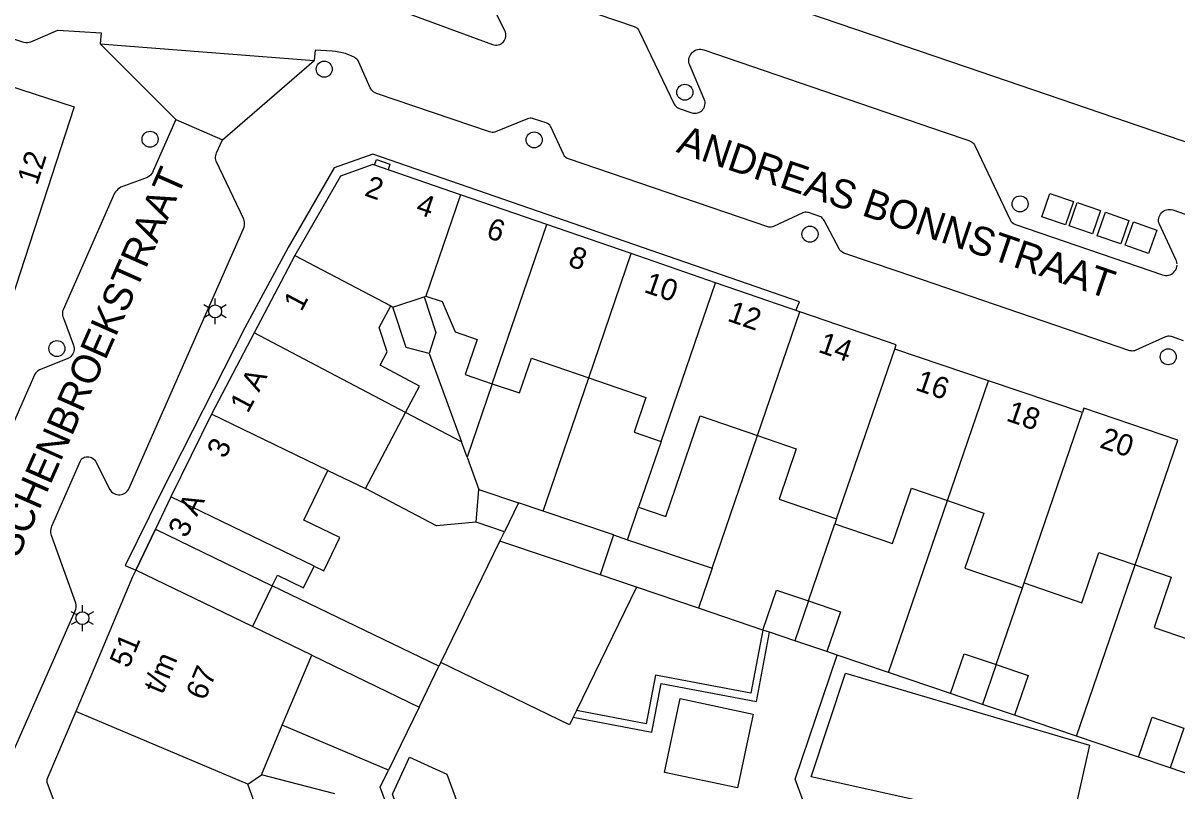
# Model space of a CAD drawing. Extents: x 122462 to 123306, y 485548 to 486417.
# Drawn here: x 122543.2 to 122623.8, y 485839.9 to 485893.5 of the extents above; entities that cross this region are included whole.
import ezdxf

# ---------------------------------------------------------------- set-up
doc = ezdxf.new("R2010")
doc.units = 0
for name, color, linetype in [('B-WE-IE-MEUBILAIR_WEGMEUBILAIR_VERKEERSBORD-S', 7, 'Continuous'), ('Level 1', 7, 'Continuous'), ('Level 10', 7, 'Continuous'), ('Level 11', 7, 'Continuous'), ('Level 17', 7, 'Continuous'), ('Level 19', 7, 'Continuous'), ('Level 2', 7, 'Continuous'), ('Level 21', 7, 'Continuous'), ('Level 4', 7, 'Continuous'), ('Level 40', 7, 'Continuous'), ('Level 42', 7, 'Continuous'), ('Level 50', 7, 'Continuous'), ('Level 53', 7, 'Continuous'), ('N werkgrens', 7, 'Continuous'), ('N-WE-AL-T25', 7, 'Continuous'), ('N-WE-GR-BOOM_DOORWORTELBARE RUIMTE-G', 7, 'Continuous')]:
    doc.layers.add(name, color=color, linetype=linetype)

msp = doc.modelspace()

# ---------------------------------------------------------------- linework, layer by layer
at = {"layer": 'Level 1'}
for p, q in [((122579.784, 485879.419), (122573.755, 485881.5)), ((122585.673, 485877.387), (122579.784, 485879.419)), ((122562.199, 485877.259), (122559.357, 485871.865)), ((122591.562, 485875.354), (122585.673, 485877.387)), ((122597.449, 485873.319), (122591.562, 485875.354)), ((122569.031, 485873.661), (122571.216, 485874.378)), ((122571.216, 485874.378), (122571.328, 485874.415)), ((122568.882, 485873.74), (122569.031, 485873.661)), ((122559.357, 485871.865), (122556.36, 485866.179)), ((122610.631, 485868.505), (122604.076, 485870.72)), ((122617.186, 485866.29), (122610.631, 485868.505)), ((122567.125, 485860.979), (122569.927, 485866.294)), ((122556.36, 485866.179), (122553.539, 485860.4)), ((122587.764, 485864.269), (122586.194, 485859.684)), ((122564.499, 485862.248), (122567.125, 485860.979)), ((122553.539, 485860.4), (122552.459, 485858.14)), ((122600.02, 485858.876), (122599.901, 485858.529)), ((122552.459, 485858.14), (122560.61, 485854.202)), ((122563.373, 485849.35), (122551.08, 485855.289)), ((122612.992, 485854.044), (122613.111, 485854.392)), ((122561.31, 485844.461), (122563.373, 485849.35)), ((122559.851, 485841.002), (122561.31, 485844.461)), ((122558.901, 485840.349), (122559.851, 485841.002)), ((122559.59, 485838.478), (122558.901, 485840.349))]:
    msp.add_line(p, q, dxfattribs=at)
for points in [[(122579.039, 485900.679), (122609.071, 485890.432), (122627.809, 485884.039), (122627.989, 485884.549), (122627.707, 485884.649), (122627.853, 485885.077)], [(122531.929, 485892.459), (122546.779, 485887.63), (122540.489, 485868.38)], [(122573.755, 485881.5), (122567.64, 485883.61), (122565.37, 485882.799), (122562.199, 485877.259)], [(122571.328, 485874.415), (122572.473, 485874.048), (122573.373, 485871.919), (122574.92, 485871.389), (122574.086, 485868.954), (122575.978, 485868.306)], [(122569.927, 485866.294), (122570.9, 485868.14), (122568.142, 485869.594), (122568.637, 485870.533), (122568.081, 485872.22), (122568.882, 485873.74)], [(122604.076, 485870.72), (122604.179, 485871.029), (122602.696, 485871.534), (122597.449, 485873.319)], [(122575.978, 485868.306), (122577.871, 485867.658), (122578.705, 485870.092), (122582.706, 485868.722)], [(122582.706, 485868.722), (122586.707, 485867.351), (122585.873, 485864.917), (122587.764, 485864.269)], [(122623.84, 485864.36), (122617.289, 485866.6), (122617.186, 485866.29)], [(122586.194, 485859.684), (122588.087, 485859.036), (122590.492, 485866.055), (122594.493, 485864.685)], [(122594.493, 485864.685), (122597.2, 485863.758), (122596, 485860.253), (122600.02, 485858.876)], [(122563.528, 485855.575), (122564.206, 485855.248), (122565.327, 485857.569), (122562.823, 485858.78), (122564.499, 485862.248)], [(122599.901, 485858.529), (122603.921, 485857.152), (122605.24, 485861.004), (122607.765, 485860.139)], [(122607.765, 485860.139), (122610.292, 485859.274), (122608.972, 485855.42), (122612.992, 485854.044)], [(122613.111, 485854.392), (122617.132, 485853.015), (122618.333, 485856.521), (122620.859, 485855.655)], [(122551.08, 485855.289), (122550.86, 485854.829), (122548.166, 485848.445), (122546.889, 485845.419)], [(122560.61, 485854.202), (122560.969, 485854.946), (122562.797, 485854.062), (122563.528, 485855.575)], [(122620.859, 485855.655), (122623.385, 485854.79), (122622.185, 485851.285), (122626.205, 485849.908)], [(122546.889, 485845.419), (122544.88, 485840.66), (122544.88, 485840.489), (122548.508, 485830.759)]]:
    msp.add_lwpolyline(points, dxfattribs=at)
at = {"layer": 'Level 10'}
msp.add_lwpolyline([(122551.08, 485855.289), (122552.459, 485858.14), (122560.61, 485854.202), (122559.232, 485851.352), (122551.08, 485855.289)], dxfattribs=at)
at = {"layer": 'Level 11'}
msp.add_lwpolyline([(122597.176, 485873.416), (122597.427, 485874.032), (122567.638, 485884.325), (122564.924, 485883.389), (122561.714, 485877.82), (122558.692, 485872.216), (122552.845, 485860.698), (122550.35, 485855.621), (122551.08, 485855.289)], dxfattribs=at)
at = {"layer": 'Level 17'}
for p, q in [((122548.595, 485892.043), (122553.885, 485886.747)), ((122548.595, 485892.043), (122563.545, 485890.867)), ((122557.131, 485885.342), (122563.545, 485890.867)), ((122553.885, 485886.747), (122557.131, 485885.342)), ((122552.459, 485858.14), (122551.08, 485855.289))]:
    msp.add_line(p, q, dxfattribs=at)
for points in [[(122576.695, 485896.389), (122585.892, 485893.241), (122585.979, 485893.203), (122586.06, 485893.151), (122586.131, 485893.088), (122586.191, 485893.014), (122586.239, 485892.932), (122588.681, 485887.836), (122588.729, 485887.754), (122588.789, 485887.68), (122588.86, 485887.617), (122588.941, 485887.566), (122589.028, 485887.528), (122589.909, 485887.227), (122590.006, 485887.201), (122590.106, 485887.19), (122590.207, 485887.193), (122590.306, 485887.21), (122590.402, 485887.242), (122590.492, 485887.286), (122590.575, 485887.344), (122590.649, 485887.413), (122590.712, 485887.491), (122590.763, 485887.578), (122590.801, 485887.671), (122590.825, 485887.769), (122590.835, 485887.869), (122590.831, 485887.97), (122590.812, 485888.069), (122590.779, 485888.164), (122589.761, 485890.549), (122589.725, 485890.651), (122589.704, 485890.757), (122589.697, 485890.865), (122589.705, 485890.973), (122589.727, 485891.079), (122589.763, 485891.181), (122589.813, 485891.277), (122589.875, 485891.366), (122589.948, 485891.445), (122590.032, 485891.514), (122590.124, 485891.571), (122590.223, 485891.615), (122590.327, 485891.645), (122590.434, 485891.661)], [(122569.21, 485894.489), (122575.986, 485891.987), (122576.086, 485891.958), (122576.189, 485891.945), (122576.293, 485891.946), (122576.396, 485891.964), (122576.495, 485891.996), (122576.588, 485892.042), (122576.673, 485892.102), (122576.748, 485892.174), (122576.812, 485892.256), (122576.863, 485892.347), (122576.9, 485892.444), (122576.922, 485892.546), (122576.929, 485892.649), (122576.921, 485892.753), (122576.897, 485892.854), (122576.858, 485892.951), (122575.699, 485895.32)], [(122534.539, 485895.051), (122543.162, 485892.177), (122543.277, 485892.147), (122543.395, 485892.133), (122543.513, 485892.134), (122543.631, 485892.151), (122543.745, 485892.182), (122545.646, 485892.994), (122548.673, 485892.799), (122548.595, 485892.043)], [(122600.372, 485877.511), (122600.303, 485877.57), (122600.243, 485877.638), (122600.195, 485877.715), (122599.141, 485879.71), (122599.097, 485879.78), (122599.044, 485879.844), (122598.982, 485879.9), (122598.913, 485879.947), (122598.839, 485879.984), (122598.067, 485880.249), (122597.987, 485880.27), (122597.904, 485880.28), (122597.821, 485880.279), (122597.739, 485880.266), (122597.659, 485880.242), (122595.618, 485879.285), (122595.54, 485879.255), (122595.459, 485879.236), (122595.377, 485879.229), (122595.294, 485879.233), (122595.212, 485879.248), (122581.293, 485884.002), (122581.203, 485884.041), (122581.121, 485884.094), (122581.049, 485884.16), (122580.988, 485884.237), (122580.94, 485884.322), (122580.091, 485886.192), (122580.044, 485886.277), (122579.983, 485886.354), (122579.911, 485886.42), (122579.829, 485886.473), (122579.739, 485886.512), (122578.865, 485886.811), (122578.782, 485886.833), (122578.697, 485886.843), (122578.611, 485886.84), (122578.527, 485886.825), (122578.445, 485886.799), (122576.211, 485885.893), (122576.13, 485885.867), (122576.045, 485885.852), (122575.96, 485885.85), (122575.875, 485885.86), (122575.792, 485885.882), (122567.898, 485888.57), (122567.803, 485888.61), (122567.714, 485888.662), (122567.633, 485888.726), (122567.562, 485888.801), (122567.502, 485888.885), (122567.454, 485888.976), (122566.667, 485890.747), (122566.627, 485890.826), (122566.578, 485890.899), (122566.52, 485890.966), (122566.455, 485891.025), (122566.383, 485891.076), (122566.169, 485891.181), (122565.949, 485891.273), (122565.724, 485891.352), (122565.494, 485891.416), (122565.261, 485891.467), (122565.025, 485891.503), (122564.788, 485891.525), (122563.62, 485891.6), (122563.545, 485890.867)], [(122590.434, 485891.661), (122590.542, 485891.662), (122590.649, 485891.649), (122590.754, 485891.621), (122607.533, 485885.874), (122609.251, 485885.286), (122609.346, 485885.25), (122609.435, 485885.2), (122609.516, 485885.139), (122609.588, 485885.067), (122609.649, 485884.986), (122609.698, 485884.897), (122612.139, 485879.744), (122612.194, 485879.66), (122612.261, 485879.585), (122612.338, 485879.52), (122612.422, 485879.466), (122612.514, 485879.424), (122622.778, 485875.903), (122622.882, 485875.876), (122622.989, 485875.865), (122623.096, 485875.868), (122623.202, 485875.885), (122623.304, 485875.918), (122623.401, 485875.964), (122623.49, 485876.023), (122623.571, 485876.095), (122623.64, 485876.176), (122623.698, 485876.267), (122623.743, 485876.364), (122623.773, 485876.467), (122623.789, 485876.573)], [(122553.885, 485886.747), (122552.306, 485883.166), (122552.255, 485883.06), (122552.19, 485882.961), (122552.112, 485882.872), (122552.024, 485882.794), (122551.926, 485882.729), (122551.82, 485882.677), (122550.046, 485882.033), (122549.939, 485881.968), (122549.84, 485881.892), (122549.749, 485881.806), (122549.668, 485881.71), (122549.597, 485881.607), (122546.006, 485873.474), (122545.976, 485873.376), (122545.959, 485873.275), (122545.957, 485873.173), (122545.968, 485873.072), (122545.993, 485872.973), (122546.032, 485872.878), (122546.732, 485871.003), (122546.762, 485870.9), (122546.778, 485870.794), (122546.777, 485870.686), (122546.761, 485870.58), (122546.73, 485870.478), (122546.685, 485870.38), (122546.625, 485870.291), (122546.554, 485870.211), (122546.471, 485870.142), (122546.38, 485870.086), (122546.281, 485870.044), (122544.365, 485869.28), (122544.286, 485869.236), (122544.213, 485869.183), (122544.148, 485869.12), (122544.091, 485869.05), (122544.044, 485868.973), (122540.594, 485861.168)], [(122546.893, 485852.552), (122546.915, 485852.657), (122546.922, 485852.764), (122546.912, 485852.871), (122546.887, 485852.976), (122545.207, 485857.701), (122545.176, 485857.809), (122545.159, 485857.921), (122545.156, 485858.033), (122545.167, 485858.145), (122545.192, 485858.255), (122545.23, 485858.361), (122547.218, 485862.926), (122547.276, 485863.004), (122547.346, 485863.071), (122547.426, 485863.127), (122547.513, 485863.169), (122547.607, 485863.196), (122547.703, 485863.208), (122547.8, 485863.205), (122547.895, 485863.187), (122547.987, 485863.153), (122548.071, 485863.106), (122548.147, 485863.045), (122548.213, 485862.973), (122548.266, 485862.892), (122548.305, 485862.803), (122549.264, 485860.925), (122549.322, 485860.837), (122549.392, 485860.757), (122549.473, 485860.689), (122549.562, 485860.632), (122549.658, 485860.588), (122549.76, 485860.559), (122549.865, 485860.544), (122549.97, 485860.544), (122550.075, 485860.558), (122550.177, 485860.587), (122550.273, 485860.631), (122550.363, 485860.687), (122550.444, 485860.755), (122550.514, 485860.834), (122550.572, 485860.923), (122550.618, 485861.018), (122558.654, 485879.226), (122558.676, 485879.341), (122558.684, 485879.458), (122558.679, 485879.575), (122558.659, 485879.691), (122558.626, 485879.803), (122556.702, 485883.84), (122556.674, 485883.934), (122556.658, 485884.031), (122556.654, 485884.13), (122556.663, 485884.227), (122556.685, 485884.323), (122556.718, 485884.416), (122557.131, 485885.342)], [(122623.791, 485876.681), (122623.777, 485876.787), (122623.748, 485876.89), (122623.706, 485876.989), (122622.554, 485879.44), (122622.521, 485879.541), (122622.503, 485879.646), (122622.5, 485879.753), (122622.512, 485879.859), (122622.538, 485879.962), (122622.579, 485880.061), (122622.634, 485880.152), (122622.701, 485880.235), (122622.779, 485880.308), (122622.867, 485880.369), (122622.962, 485880.416), (122623.063, 485880.45), (122623.168, 485880.469), (122623.274, 485880.474), (122623.381, 485880.463), (122623.484, 485880.437), (122627.732, 485878.954)], [(122624.231, 485871.308), (122623.401, 485871.592), (122623.321, 485871.613), (122623.238, 485871.623), (122623.155, 485871.622), (122623.073, 485871.609), (122622.994, 485871.585), (122620.905, 485870.639), (122620.827, 485870.61), (122620.746, 485870.592), (122620.663, 485870.585), (122620.58, 485870.59), (122620.499, 485870.606), (122604.255, 485876.156), (122600.532, 485877.428), (122600.449, 485877.464), (122600.372, 485877.511)], [(122542.531, 485842.602), (122545.6, 485849.59), (122546.856, 485852.451), (122546.893, 485852.552)]]:
    msp.add_lwpolyline(points, dxfattribs=at)
at = {"layer": 'Level 19'}
for p, q in [((122571.559, 485870.416), (122573.827, 485864.238)), ((122579.517, 485859.408), (122582.706, 485868.722)), ((122575.978, 485868.306), (122574.219, 485863.17)), ((122573.827, 485864.238), (122569.927, 485866.294)), ((122591.318, 485855.414), (122594.493, 485864.685)), ((122574.219, 485863.17), (122573.827, 485864.238)), ((122574.219, 485863.17), (122575.044, 485860.923)), ((122603.652, 485848.129), (122607.765, 485860.139)), ((122585.416, 485857.411), (122586.194, 485859.684)), ((122598.053, 485853.133), (122599.901, 485858.529)), ((122616.761, 485843.691), (122620.859, 485855.655)), ((122572.254, 485848.574), (122560.61, 485854.202)), ((122611.161, 485848.694), (122612.992, 485854.044)), ((122594.874, 485851.102), (122590.364, 485852.629)), ((122563.373, 485849.35), (122570.861, 485845.709)), ((122600.057, 485849.346), (122599.326, 485849.594)), ((122603.652, 485848.129), (122600.057, 485849.346)), ((122572.385, 485848.843), (122572.254, 485848.574)), ((122607.981, 485846.664), (122603.652, 485848.129)), ((122570.861, 485845.709), (122568.731, 485841.33)), ((122616.761, 485843.691), (122612.433, 485845.157)), ((122568.731, 485841.33), (122561.31, 485844.461)), ((122621.09, 485842.225), (122616.761, 485843.691)), ((122564.979, 485839.658), (122559.851, 485841.002))]:
    msp.add_line(p, q, dxfattribs=at)
for points in [[(122571.216, 485874.378), (122572.035, 485871.882), (122571.559, 485870.416)], [(122571.559, 485870.416), (122569.959, 485870.832), (122569.031, 485873.661)], [(122574.85, 485858.629), (122572.071, 485858.372), (122567.125, 485860.979)], [(122593.099, 485840.081), (122587.999, 485841.161), (122589.091, 485846.321), (122594.191, 485845.241), (122593.099, 485840.081)], [(122568.675, 485838.69), (122568.146, 485840.126), (122568.731, 485841.33)]]:
    msp.add_lwpolyline(points, dxfattribs=at)
at = {"layer": 'Level 2'}
for p, q in [((122574.85, 485858.629), (122575.044, 485860.923)), ((122575.044, 485860.923), (122577.804, 485859.988)), ((122577.804, 485859.988), (122576.819, 485857.962)), ((122579.517, 485859.408), (122577.804, 485859.988)), ((122584.442, 485857.741), (122579.517, 485859.408)), ((122576.819, 485857.962), (122574.85, 485858.629)), ((122576.507, 485857.32), (122576.819, 485857.962)), ((122584.442, 485857.741), (122583.498, 485854.953)), ((122584.442, 485857.741), (122585.416, 485857.411)), ((122585.416, 485857.411), (122591.318, 485855.414)), ((122572.385, 485848.843), (122576.507, 485857.32)), ((122583.498, 485854.953), (122576.507, 485857.32)), ((122591.318, 485855.414), (122590.364, 485852.629)), ((122586.039, 485854.093), (122583.498, 485854.953)), ((122586.039, 485854.093), (122581.852, 485845.481)), ((122590.364, 485852.629), (122586.039, 485854.093)), ((122598.053, 485853.133), (122597.099, 485850.348)), ((122595.341, 485850.944), (122594.874, 485851.102)), ((122597.099, 485850.348), (122595.341, 485850.944)), ((122599.326, 485849.594), (122597.099, 485850.348)), ((122611.161, 485848.694), (122610.207, 485845.91)), ((122610.207, 485845.91), (122607.981, 485846.664)), ((122581.852, 485845.481), (122581.625, 485845.014)), ((122612.433, 485845.157), (122610.207, 485845.91)), ((122624.27, 485844.256), (122623.316, 485841.471)), ((122623.316, 485841.471), (122621.09, 485842.225)), ((122625.542, 485840.717), (122623.316, 485841.471))]:
    msp.add_line(p, q, dxfattribs=at)
for points in [[(122594.874, 485851.102), (122595.827, 485853.887), (122598.053, 485853.133)], [(122598.053, 485853.133), (122600.28, 485852.38), (122599.326, 485849.594)], [(122607.981, 485846.664), (122608.934, 485849.448), (122611.161, 485848.694)], [(122581.625, 485845.014), (122581.364, 485844.477), (122572.385, 485848.843)], [(122611.161, 485848.694), (122613.386, 485847.941), (122612.433, 485845.157)], [(122616.29, 485836.845), (122598.241, 485840.86), (122600.637, 485848.095), (122617.676, 485843.074), (122616.29, 485836.845)], [(122621.09, 485842.225), (122622.044, 485845.01), (122624.27, 485844.256)], [(122574.438, 485824.874), (122569, 485839.633), (122570.199, 485842.231), (122572.797, 485841.032), (122578.235, 485826.273), (122574.438, 485824.874)]]:
    msp.add_lwpolyline(points, dxfattribs=at)
at = {"layer": 'Level 21'}
for points in [[(122594.874, 485851.102), (122594.023, 485846.688), (122587.362, 485847.956), (122586.715, 485844.556), (122581.852, 485845.481)], [(122581.625, 485845.014), (122587.112, 485843.971), (122587.759, 485847.37), (122594.42, 485846.103), (122595.341, 485850.944)]]:
    msp.add_lwpolyline(points, dxfattribs=at)
at = {"layer": 'Level 4'}
for p, q in [((122575.978, 485868.306), (122579.784, 485879.419)), ((122582.706, 485868.722), (122585.673, 485877.387)), ((122587.764, 485864.269), (122591.562, 485875.354)), ((122594.493, 485864.685), (122597.449, 485873.319)), ((122569.927, 485866.294), (122559.357, 485871.865)), ((122600.02, 485858.876), (122604.076, 485870.72)), ((122607.765, 485860.139), (122610.631, 485868.505)), ((122613.111, 485854.392), (122617.186, 485866.29)), ((122564.499, 485862.248), (122556.36, 485866.179)), ((122620.859, 485855.655), (122623.84, 485864.36)), ((122558.901, 485840.349), (122546.889, 485845.419))]:
    msp.add_line(p, q, dxfattribs=at)
at = {"layer": 'Level 40'}
msp.add_lwpolyline([(122567.75, 485883.573), (122567.883, 485883.957), (122568.828, 485883.629), (122568.696, 485883.247)], dxfattribs=at)
at = {"layer": 'Level 42'}
for points in [[(122615.991, 485879.404), (122614.358, 485879.962), (122614.916, 485881.595), (122616.549, 485881.037), (122615.991, 485879.404)], [(122617.897, 485878.765), (122616.265, 485879.323), (122616.823, 485880.955), (122618.455, 485880.397), (122617.897, 485878.765)], [(122619.854, 485878.067), (122618.215, 485878.64), (122618.788, 485880.279), (122620.427, 485879.706), (122619.854, 485878.067)], [(122621.796, 485877.395), (122620.166, 485877.981), (122620.752, 485879.611), (122622.382, 485879.025), (122621.796, 485877.395)]]:
    msp.add_lwpolyline(points, dxfattribs=at)
at = {"layer": 'Level 50'}
for p, q in [((122556.233, 485873.579), (122555.843, 485873.804)), ((122556.623, 485873.804), (122556.623, 485874.254)), ((122557.402, 485873.804), (122557.012, 485873.579)), ((122556.233, 485873.129), (122555.843, 485872.904)), ((122556.623, 485872.454), (122556.623, 485872.904)), ((122557.402, 485872.904), (122557.012, 485873.129)), ((122547.358, 485852.384), (122547.358, 485852.834)), ((122546.968, 485852.159), (122546.578, 485852.384)), ((122548.137, 485852.384), (122547.747, 485852.159)), ((122546.968, 485851.709), (122546.578, 485851.484)), ((122547.358, 485851.034), (122547.358, 485851.484)), ((122548.137, 485851.484), (122547.747, 485851.709))]:
    msp.add_line(p, q, dxfattribs=at)
for centre in [(122556.623, 485873.354), (122547.358, 485851.934)]:
    msp.add_circle(centre, 0.45, dxfattribs=at)
at = {"layer": 'Level 53'}
for centre in [(122564.244, 485890.268), (122589.42, 485888.659), (122552.078, 485885.375), (122578.901, 485885.332), (122612.83, 485880.858), (122598.16, 485878.748), (122545.576, 485870.76), (122623.174, 485870.184)]:
    msp.add_circle(centre, 0.56, dxfattribs=at)
at = {"layer": 'N werkgrens'}
msp.add_line((122570.861, 485845.709), (122572.254, 485848.574), dxfattribs=at)
msp.add_lwpolyline([(122600.735, 485830.91), (122597.129, 485840.696), (122600.057, 485849.346)], dxfattribs=at)
at = {"layer": 'N-WE-AL-T25'}
for p, q in [((122573.755, 485881.5), (122571.328, 485874.415)), ((122573.755, 485881.501), (122573.755, 485881.5)), ((122562.199, 485877.259), (122568.882, 485873.74)), ((122563.528, 485855.575), (122553.539, 485860.4))]:
    msp.add_line(p, q, dxfattribs=at)

# ---------------------------------------------------------------- texts
at = {"layer": 'B-WE-IE-MEUBILAIR_WEGMEUBILAIR_VERKEERSBORD-S'}
for s, rotation, p in [('12', 71.905, (122544.189, 485882.11)), ('2', 340.95744, (122566.983, 485881.459)), ('4', 340.95744, (122570.563, 485880.222)), ('6', 340.95744, (122575.477, 485878.526)), ('8', 340.95744, (122581.198, 485876.551)), ('10', 340.95431, (122586.491, 485874.724)), ('1', 62.21284, (122562.648, 485873.283)), ('12', 340.9744, (122592.315, 485872.714)), ('14', 340.9744, (122598.664, 485870.536)), ('1 A', 62.19617, (122558.906, 485866.184)), ('16', 340.9744, (122605.442, 485867.891)), ('18', 340.9744, (122611.786, 485865.747)), ('20', 340.9744, (122618.314, 485863.878)), ('3', 63.98283, (122557.32, 485863.014)), ('3 A', 64.07066, (122554.619, 485857.472)), ('51', 67.1149, (122550.575, 485848.366)), ('t/m', 67.1149, (122552.946, 485846.551)), ('67', 67.1149, (122555.9, 485846.119))]:
    msp.add_text(s, height=1.5, rotation=rotation, dxfattribs=at).set_placement(p)
at = {"layer": 'N-WE-GR-BOOM_DOORWORTELBARE RUIMTE-G'}
for s, rotation, p in [('ANDREAS BONNSTRAAT', 341.18638, (122588.758, 485884.502)), ('VAN MUSSCHENBROEKSTRAAT', 66.15966, (122537.904, 485844.877))]:
    msp.add_text(s, height=2, rotation=rotation, dxfattribs=at).set_placement(p)

doc.saveas('drawing.dxf')
